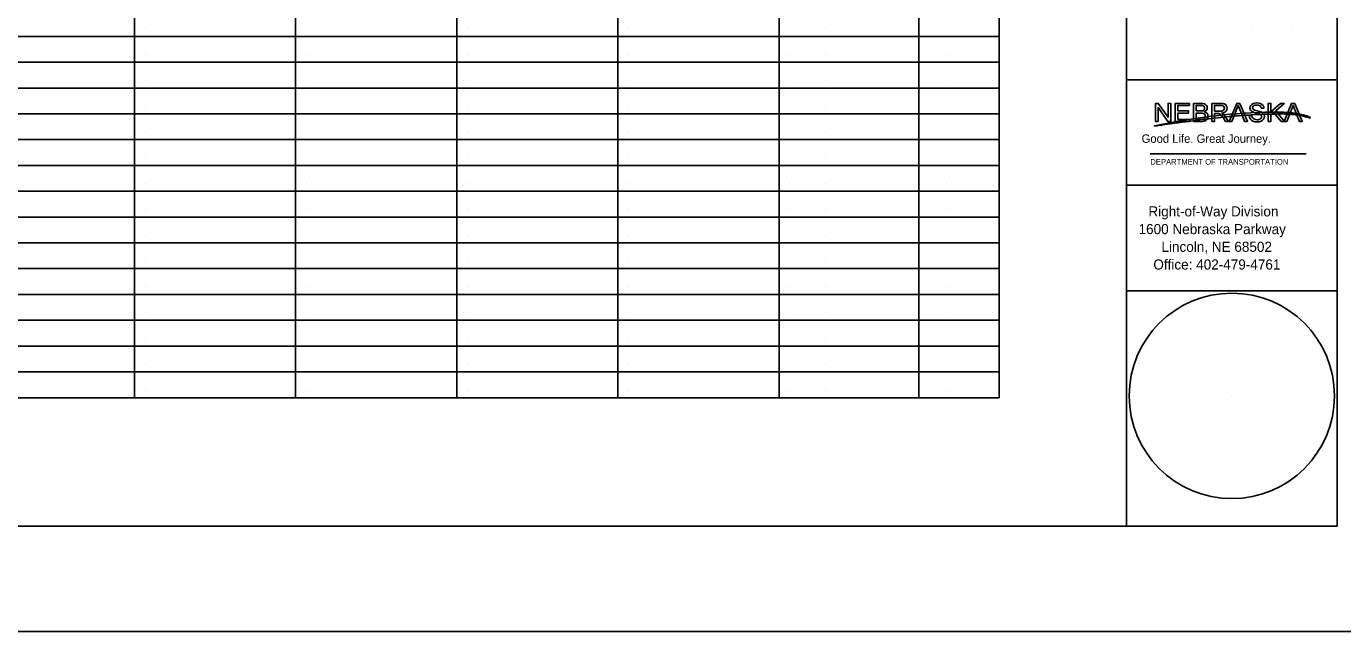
# Model space of a CAD drawing. Extents: x 0 to 3.48, y 0 to 2.25.
# Drawn here: x 1.913 to 2.954, y 0 to 0.479 of the extents above; entities that cross this region are included whole.
import ezdxf

# ---------------------------------------------------------------- set-up
doc = ezdxf.new("R2010")
doc.units = 0
for name, color, linetype in [('Border Active Points', 7, 'Continuous'), ('Border Engr Stamp', 7, 'Continuous'), ('Border Line', 7, 'Continuous'), ('Border Organizer Shape', 7, 'Continuous')]:
    doc.layers.add(name, color=color, linetype=linetype)

msp = doc.modelspace()

# ---------------------------------------------------------------- linework, layer by layer
at = {"layer": 'Border Active Points'}
for p, q in [((2.007, 0.4766), (2.007, 0.4766)), ((2.1345, 0.4766), (2.1345, 0.4766)), ((2.262, 0.4766), (2.262, 0.4766)), ((2.3895, 0.4766), (2.3895, 0.4766)), ((2.517, 0.4766), (2.517, 0.4766)), ((2.5453, 0.4766), (2.5453, 0.4766)), ((2.641, 0.4766), (2.641, 0.4766)), ((2.8247, 0.4762), (2.8247, 0.4762)), ((2.8819, 0.4762), (2.8819, 0.4762)), ((2.9138, 0.4762), (2.9138, 0.4762)), ((2.007, 0.4562), (2.007, 0.4562)), ((2.1345, 0.4562), (2.1345, 0.4562)), ((2.262, 0.4562), (2.262, 0.4562)), ((2.3895, 0.4562), (2.3895, 0.4562)), ((2.517, 0.4562), (2.517, 0.4562)), ((2.5453, 0.4562), (2.5453, 0.4562)), ((2.641, 0.4562), (2.641, 0.4562)), ((2.007, 0.4358), (2.007, 0.4358)), ((2.1345, 0.4358), (2.1345, 0.4358)), ((2.262, 0.4358), (2.262, 0.4358)), ((2.3895, 0.4358), (2.3895, 0.4358)), ((2.517, 0.4358), (2.517, 0.4358)), ((2.5453, 0.4358), (2.5453, 0.4358)), ((2.641, 0.4358), (2.641, 0.4358)), ((2.007, 0.4154), (2.007, 0.4154)), ((2.1345, 0.4154), (2.1345, 0.4154)), ((2.262, 0.4154), (2.262, 0.4154)), ((2.3895, 0.4154), (2.3895, 0.4154)), ((2.517, 0.4154), (2.517, 0.4154)), ((2.5453, 0.4154), (2.5453, 0.4154)), ((2.641, 0.4154), (2.641, 0.4154)), ((2.007, 0.395), (2.007, 0.395)), ((2.1345, 0.395), (2.1345, 0.395)), ((2.262, 0.395), (2.262, 0.395)), ((2.3895, 0.395), (2.3895, 0.395)), ((2.517, 0.395), (2.517, 0.395)), ((2.5453, 0.395), (2.5453, 0.395)), ((2.641, 0.395), (2.641, 0.395)), ((2.007, 0.3746), (2.007, 0.3746)), ((2.1345, 0.3746), (2.1345, 0.3746)), ((2.262, 0.3746), (2.262, 0.3746)), ((2.3895, 0.3746), (2.3895, 0.3746)), ((2.517, 0.3746), (2.517, 0.3746)), ((2.5453, 0.3746), (2.5453, 0.3746)), ((2.641, 0.3746), (2.641, 0.3746)), ((2.007, 0.3542), (2.007, 0.3542)), ((2.1345, 0.3542), (2.1345, 0.3542)), ((2.262, 0.3542), (2.262, 0.3542)), ((2.3895, 0.3542), (2.3895, 0.3542)), ((2.517, 0.3542), (2.517, 0.3542)), ((2.5453, 0.3542), (2.5453, 0.3542)), ((2.641, 0.3542), (2.641, 0.3542)), ((2.007, 0.3338), (2.007, 0.3338)), ((2.1345, 0.3338), (2.1345, 0.3338)), ((2.262, 0.3338), (2.262, 0.3338)), ((2.3895, 0.3338), (2.3895, 0.3338)), ((2.517, 0.3338), (2.517, 0.3338)), ((2.5453, 0.3338), (2.5453, 0.3338)), ((2.641, 0.3338), (2.641, 0.3338)), ((2.007, 0.3134), (2.007, 0.3134)), ((2.1345, 0.3134), (2.1345, 0.3134)), ((2.262, 0.3134), (2.262, 0.3134)), ((2.3895, 0.3134), (2.3895, 0.3134)), ((2.517, 0.3134), (2.517, 0.3134)), ((2.5453, 0.3134), (2.5453, 0.3134)), ((2.641, 0.3134), (2.641, 0.3134)), ((2.8667, 0.3113), (2.8667, 0.3113)), ((2.007, 0.293), (2.007, 0.293)), ((2.1345, 0.293), (2.1345, 0.293)), ((2.262, 0.293), (2.262, 0.293)), ((2.3895, 0.293), (2.3895, 0.293)), ((2.517, 0.293), (2.517, 0.293)), ((2.5453, 0.293), (2.5453, 0.293)), ((2.641, 0.293), (2.641, 0.293)), ((2.007, 0.2726), (2.007, 0.2726)), ((2.1345, 0.2726), (2.1345, 0.2726)), ((2.262, 0.2726), (2.262, 0.2726)), ((2.3895, 0.2726), (2.3895, 0.2726)), ((2.517, 0.2726), (2.517, 0.2726)), ((2.5453, 0.2726), (2.5453, 0.2726)), ((2.641, 0.2726), (2.641, 0.2726)), ((2.007, 0.2522), (2.007, 0.2522)), ((2.1345, 0.2522), (2.1345, 0.2522)), ((2.262, 0.2522), (2.262, 0.2522)), ((2.3895, 0.2522), (2.3895, 0.2522)), ((2.517, 0.2522), (2.517, 0.2522)), ((2.5453, 0.2522), (2.5453, 0.2522)), ((2.641, 0.2522), (2.641, 0.2522)), ((2.007, 0.2318), (2.007, 0.2318)), ((2.1345, 0.2318), (2.1345, 0.2318)), ((2.262, 0.2318), (2.262, 0.2318)), ((2.3895, 0.2318), (2.3895, 0.2318)), ((2.517, 0.2318), (2.517, 0.2318)), ((2.5453, 0.2318), (2.5453, 0.2318)), ((2.641, 0.2318), (2.641, 0.2318)), ((2.007, 0.2114), (2.007, 0.2114)), ((2.1345, 0.2114), (2.1345, 0.2114)), ((2.262, 0.2114), (2.262, 0.2114)), ((2.3895, 0.2114), (2.3895, 0.2114)), ((2.517, 0.2114), (2.517, 0.2114)), ((2.5453, 0.2114), (2.5453, 0.2114)), ((2.641, 0.2114), (2.641, 0.2114)), ((2.007, 0.191), (2.007, 0.191)), ((2.1345, 0.191), (2.1345, 0.191)), ((2.262, 0.191), (2.262, 0.191)), ((2.3895, 0.191), (2.3895, 0.191)), ((2.517, 0.191), (2.517, 0.191)), ((2.5453, 0.191), (2.5453, 0.191)), ((2.641, 0.191), (2.641, 0.191)), ((2.8667, 0.1864), (2.8667, 0.1864))]:
    msp.add_line(p, q, dxfattribs=at)
at = {"layer": 'Border Engr Stamp'}
msp.add_circle((2.8667, 0.1864), 0.0812, dxfattribs=at)
at = {"layer": 'Border Line'}
for p, q in [((2.7834, 0.0835), (2.7834, 1.9165)), ((2.6827, 1.681), (2.6827, 0.185)), ((1.9985, 1.6555), (1.9985, 0.185)), ((2.2535, 1.6555), (2.2535, 0.185)), ((2.5085, 1.6555), (2.5085, 0.185)), ((2.619, 1.6555), (2.619, 0.185)), ((2.126, 1.6342), (2.126, 0.185)), ((2.381, 1.6342), (2.381, 0.185)), ((0.2177, 0.4706), (2.6827, 0.4706)), ((0.2177, 0.4502), (2.6827, 0.4502)), ((0.2177, 0.4298), (2.6827, 0.4298)), ((2.7834, 0.4362), (2.95, 0.4362)), ((0.2177, 0.4094), (2.6827, 0.4094)), ((2.9288, 0.4064), (2.9288, 0.4064)), ((0.2177, 0.389), (2.6827, 0.389)), ((2.8021, 0.3779), (2.9256, 0.3779)), ((0.2177, 0.3686), (2.6827, 0.3686)), ((0.2177, 0.3482), (2.6827, 0.3482)), ((2.7834, 0.3529), (2.95, 0.3529)), ((0.2177, 0.3278), (2.6827, 0.3278)), ((0.2177, 0.3074), (2.6827, 0.3074)), ((0.2177, 0.287), (2.6827, 0.287)), ((0.2177, 0.2666), (2.6827, 0.2666)), ((2.7834, 0.2696), (2.95, 0.2696)), ((0.2177, 0.2462), (2.6827, 0.2462)), ((0.2177, 0.2258), (2.6827, 0.2258)), ((0.2177, 0.2054), (2.6827, 0.2054)), ((0.217, 0.185), (2.6827, 0.185))]:
    msp.add_line(p, q, dxfattribs=at)
for points in [[(0.117, 0.0835), (2.95, 0.0835), (2.95, 1.9165), (0.117, 1.9165)], [(2.8063, 0.4034), (2.8084, 0.4034), (2.8084, 0.4144), (2.8161, 0.4034), (2.8183, 0.4034), (2.8183, 0.4177), (2.8162, 0.4177), (2.8162, 0.4067), (2.8085, 0.4177), (2.8063, 0.4177)], [(2.8219, 0.4034), (2.8334, 0.4034), (2.8334, 0.405), (2.824, 0.405), (2.824, 0.41), (2.8325, 0.41), (2.8325, 0.4117), (2.824, 0.4117), (2.824, 0.4161), (2.8331, 0.4161), (2.8331, 0.4177), (2.8219, 0.4177)], [(2.8646, 0.4034), (2.8668, 0.4034), (2.8718, 0.4161), (2.875, 0.4078), (2.8768, 0.4034), (2.879, 0.4034), (2.873, 0.4177), (2.8706, 0.4177)], [(2.8804, 0.4081), (2.8806, 0.4067), (2.8812, 0.4054), (2.8822, 0.4044), (2.8834, 0.4037), (2.885, 0.4032), (2.8868, 0.4031), (2.8884, 0.4032), (2.8898, 0.4037), (2.8909, 0.4043), (2.8917, 0.4052), (2.8923, 0.4063), (2.8924, 0.4074), (2.8923, 0.4085), (2.8918, 0.4095), (2.891, 0.4103), (2.8899, 0.4109), (2.8866, 0.4119), (2.8847, 0.4124), (2.8837, 0.4129), (2.8832, 0.4135), (2.8831, 0.4142), (2.8833, 0.415), (2.8839, 0.4157), (2.8849, 0.4162), (2.8865, 0.4164), (2.8879, 0.4162), (2.889, 0.4157), (2.8897, 0.4149), (2.89, 0.4139), (2.8921, 0.4139), (2.8919, 0.415), (2.8914, 0.4161), (2.8905, 0.4169), (2.8894, 0.4175), (2.888, 0.4179), (2.8864, 0.418), (2.8849, 0.4179), (2.8836, 0.4175), (2.8825, 0.4169), (2.8817, 0.4161), (2.8812, 0.4151), (2.881, 0.414), (2.8811, 0.4131), (2.8815, 0.4122), (2.8822, 0.4115), (2.8832, 0.4109), (2.8844, 0.4104), (2.8861, 0.41), (2.8887, 0.4093), (2.8895, 0.4089), (2.89, 0.4084), (2.8902, 0.4079), (2.8903, 0.4072), (2.8902, 0.4066), (2.8899, 0.406), (2.8894, 0.4055), (2.8887, 0.4051), (2.8878, 0.4048), (2.8868, 0.4048), (2.8856, 0.4049), (2.8845, 0.4052), (2.8837, 0.4057), (2.8831, 0.4063), (2.8827, 0.4071), (2.8825, 0.4081)], [(2.8955, 0.4034), (2.8976, 0.4034), (2.8976, 0.4084), (2.8999, 0.4104), (2.9058, 0.4034), (2.9084, 0.4034), (2.9014, 0.4117), (2.9081, 0.4177), (2.9052, 0.4177), (2.8976, 0.4109), (2.8976, 0.4177), (2.8955, 0.4177)], [(2.908, 0.4034), (2.9102, 0.4034), (2.9152, 0.4161), (2.9184, 0.4078), (2.9202, 0.4034), (2.9224, 0.4034), (2.9164, 0.4177), (2.9139, 0.4177)]]:
    msp.add_lwpolyline(points, close=True, dxfattribs=at)
for points in [[(2.8364, 0.4034), (2.8422, 0.4034), (2.8435, 0.4034), (2.8446, 0.4036), (2.8455, 0.4039), (2.8463, 0.4043), (2.8469, 0.4049), (2.8474, 0.4057), (2.8477, 0.4066), (2.8478, 0.4076), (2.8477, 0.4088), (2.8471, 0.4098), (2.8462, 0.4106), (2.845, 0.4111), (2.846, 0.4117), (2.8467, 0.4124), (2.8471, 0.4132), (2.8472, 0.4141), (2.8471, 0.4151), (2.8466, 0.416), (2.8459, 0.4168), (2.845, 0.4173), (2.8437, 0.4176), (2.8422, 0.4177), (2.8364, 0.4177), (2.8364, 0.4034)], [(2.8509, 0.4034), (2.853, 0.4034), (2.853, 0.4097), (2.8553, 0.4097), (2.8564, 0.4097), (2.8573, 0.4093), (2.8583, 0.4084), (2.8597, 0.4064), (2.8617, 0.4034), (2.8641, 0.4034), (2.8615, 0.4073), (2.8599, 0.4093), (2.8587, 0.41), (2.8606, 0.4105), (2.8619, 0.4113), (2.8627, 0.4125), (2.8629, 0.4139), (2.8628, 0.415), (2.8623, 0.416), (2.8616, 0.4168), (2.8606, 0.4174), (2.8594, 0.4176), (2.8576, 0.4177), (2.8509, 0.4177), (2.8509, 0.4034)], [(2.8385, 0.4117), (2.8385, 0.4161), (2.8415, 0.4161), (2.8429, 0.416), (2.8438, 0.4159), (2.8443, 0.4156), (2.8448, 0.4151), (2.845, 0.4145), (2.8451, 0.4138), (2.845, 0.4131), (2.8448, 0.4126), (2.8443, 0.4121), (2.8436, 0.4118), (2.8417, 0.4117), (2.8385, 0.4117)], [(2.8385, 0.405), (2.8385, 0.41), (2.842, 0.41), (2.8432, 0.4099), (2.8441, 0.4098), (2.8448, 0.4094), (2.8453, 0.4089), (2.8456, 0.4083), (2.8457, 0.4075), (2.8457, 0.4069), (2.8454, 0.4063), (2.8447, 0.4055), (2.8436, 0.4051), (2.8422, 0.405), (2.8385, 0.405)], [(2.853, 0.4114), (2.853, 0.4161), (2.8577, 0.4161), (2.8591, 0.4159), (2.8601, 0.4154), (2.8606, 0.4147), (2.8608, 0.4138), (2.8607, 0.4131), (2.8604, 0.4125), (2.8599, 0.412), (2.8593, 0.4117), (2.8584, 0.4115), (2.8572, 0.4114), (2.853, 0.4114)], [(2.9288, 0.4064), (2.9288, 0.4064)]]:
    msp.add_lwpolyline(points, dxfattribs=at)
for centre, radius, start, end in [((2.9083, -0.0701), 0.4811, 91.855, 102.3361), ((2.9083, -0.0701), 0.4811, 91.855, 102.3361), ((2.9287, 0.4063), 0.000147, 257.514, 70.0232), ((2.9287, 0.4063), 0.000147, 70.0232, 72.6492), ((2.8056, 0.3998), 0.00012, 160.636, 260.4589)]:
    msp.add_arc(centre, radius, start, end, dxfattribs=at)
for points in [[(2.8056, 0.3997), (2.8089, 0.4002), (2.8182, 0.4016), (2.8303, 0.4032), (2.8596, 0.4067), (2.872, 0.4079), (2.8922, 0.4091), (2.9055, 0.4093), (2.9129, 0.4091), (2.9235, 0.4075), (2.9287, 0.4061)], [(2.9288, 0.4064), (2.9278, 0.4069), (2.9265, 0.4075), (2.9241, 0.4083), (2.923, 0.4086), (2.921, 0.409), (2.9173, 0.4097), (2.9143, 0.4101), (2.912, 0.4104), (2.9097, 0.4105), (2.9083, 0.4106), (2.9069, 0.4107), (2.9042, 0.4108), (2.8927, 0.4107)]]:
    msp.add_spline(points, degree=3, dxfattribs=at)
at = {"layer": 'Border Organizer Shape'}
msp.add_lwpolyline([(3, 0), (0, 0), (0, 2), (3, 2)], close=True, dxfattribs=at)

# ---------------------------------------------------------------- texts
at = {"layer": 'Border Line'}
for s, height, p in [('Good Life. Great Journey.', 0.006653, (2.7953, 0.3865)), ('DEPARTMENT OF TRANSPORTATION', 0.004524, (2.8022, 0.3692)), ('Right-of-Way Division', 0.008, (2.8007, 0.3283)), ('1600 Nebraska Parkway', 0.008, (2.7929, 0.3143)), ('Lincoln, NE 68502', 0.008, (2.811, 0.3003)), ('Office: 402-479-4761', 0.008, (2.8046, 0.2863))]:
    msp.add_text(s, height=height, dxfattribs=at).set_placement(p)

doc.saveas('drawing.dxf')
